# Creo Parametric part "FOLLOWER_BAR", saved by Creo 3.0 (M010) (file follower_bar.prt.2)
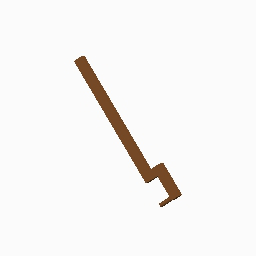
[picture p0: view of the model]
Units: millimeter Kilogram Sec (mmKs); MM, KILOGRAM, SECS

Created from: SOLID_PART_MMKS.PRT

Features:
  1. coordinate system
  2. datum plane "RIGHT"
  3. datum plane "TOP"
  4. datum plane "FRONT"
  5. sketch "Sketch 1"
  6. extrusion "Extrude 1"
  7. sketch "Sketch 2"
  8. extrusion "Extrude 2"

Surfaces: 14 plane, 2 cylinder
